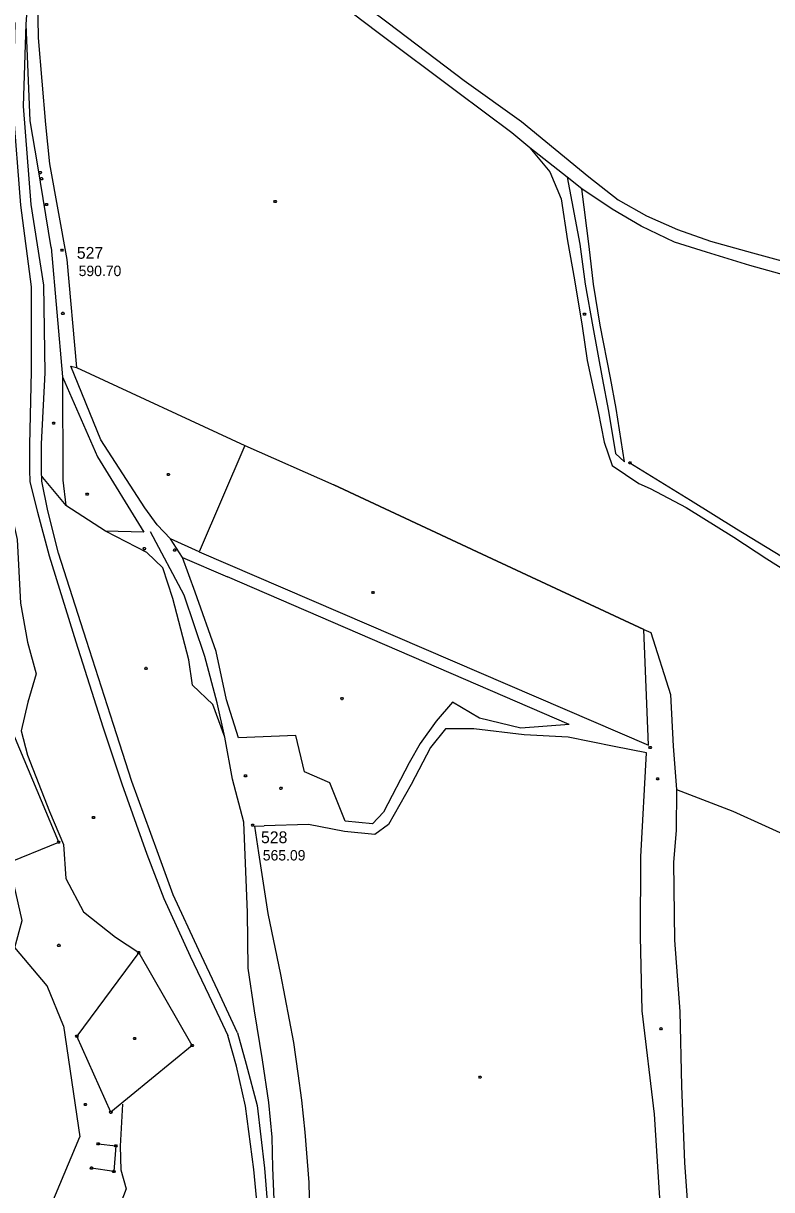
# Model space of a CAD drawing. Extents: x -664960 to -662754, y -993849 to -991145.
# Drawn here: x -663722.6 to -663507.3, y -991825.9 to -991490.5 of the extents above; entities that cross this region are included whole.
import ezdxf

# ---------------------------------------------------------------- set-up
doc = ezdxf.new("R2010")
doc.units = 0
for name, color, linetype in [('Vrstva 1', 7, 'Continuous'), ('Vrstva 12', 7, 'Continuous'), ('Vrstva 13', 7, 'Continuous'), ('Vrstva 18', 7, 'Continuous'), ('Vrstva 27', 7, 'Continuous'), ('Vrstva 28', 7, 'Continuous'), ('Vrstva 63', 7, 'Continuous'), ('Vrstva 8', 7, 'Continuous')]:
    doc.layers.add(name, color=color, linetype=linetype)

msp = doc.modelspace()

# ---------------------------------------------------------------- linework, layer by layer
at = {"layer": 'Vrstva 12'}
for p in [(-663684.075, -991634.708), (-663680.28, -991638.751), (-663672.011, -991642.462)]:
    msp.add_line(p, (-663680.28, -991638.751), dxfattribs=at)
for points in [[(-663684.075, -991634.708), (-663687.678, -991629.824), (-663700.338, -991610.256), (-663708.929, -991589.067), (-663707.354, -991589.5)], [(-663707.354, -991589.5), (-663658.913, -991611.926), (-663672.011, -991642.462)]]:
    msp.add_lwpolyline(points, dxfattribs=at)
at = {"layer": 'Vrstva 13'}
for points in [[(-663649.982, -991541.386), (-663649.802, -991541.686), (-663649.982, -991541.986), (-663650.342, -991541.986), (-663650.522, -991541.686), (-663650.342, -991541.386), (-663649.982, -991541.386)], [(-663711.068, -991573.584), (-663710.888, -991573.884), (-663711.068, -991574.184), (-663711.428, -991574.184), (-663711.608, -991573.884), (-663711.428, -991573.584), (-663711.068, -991573.584)], [(-663560.997, -991573.818), (-663560.817, -991574.118), (-663560.997, -991574.418), (-663561.357, -991574.418), (-663561.537, -991574.118), (-663561.357, -991573.818), (-663560.997, -991573.818)], [(-663713.701, -991605.203), (-663713.521, -991605.503), (-663713.701, -991605.803), (-663714.061, -991605.803), (-663714.241, -991605.503), (-663714.061, -991605.203), (-663713.701, -991605.203)], [(-663680.701, -991619.947), (-663680.521, -991620.247), (-663680.701, -991620.547), (-663681.061, -991620.547), (-663681.241, -991620.247), (-663681.061, -991619.947), (-663680.701, -991619.947)], [(-663704.096, -991625.594), (-663703.916, -991625.894), (-663704.096, -991626.194), (-663704.456, -991626.194), (-663704.636, -991625.894), (-663704.456, -991625.594), (-663704.096, -991625.594)], [(-663687.611, -991641.256), (-663687.431, -991641.556), (-663687.611, -991641.856), (-663687.971, -991641.856), (-663688.151, -991641.556), (-663687.971, -991641.256), (-663687.611, -991641.256)], [(-663621.856, -991653.843), (-663621.676, -991654.143), (-663621.856, -991654.443), (-663622.216, -991654.443), (-663622.396, -991654.143), (-663622.216, -991653.843), (-663621.856, -991653.843)], [(-663687.156, -991675.684), (-663686.976, -991675.984), (-663687.156, -991676.284), (-663687.516, -991676.284), (-663687.696, -991675.984), (-663687.516, -991675.684), (-663687.156, -991675.684)], [(-663630.759, -991684.39), (-663630.579, -991684.69), (-663630.759, -991684.99), (-663631.119, -991684.99), (-663631.299, -991684.69), (-663631.119, -991684.39), (-663630.759, -991684.39)], [(-663539.96, -991707.462), (-663539.78, -991707.762), (-663539.96, -991708.062), (-663540.32, -991708.062), (-663540.5, -991707.762), (-663540.32, -991707.462), (-663539.96, -991707.462)], [(-663648.325, -991710.182), (-663648.145, -991710.482), (-663648.325, -991710.782), (-663648.685, -991710.782), (-663648.865, -991710.482), (-663648.685, -991710.182), (-663648.325, -991710.182)], [(-663702.27, -991718.559), (-663702.09, -991718.859), (-663702.27, -991719.159), (-663702.63, -991719.159), (-663702.81, -991718.859), (-663702.63, -991718.559), (-663702.27, -991718.559)], [(-663712.237, -991755.339), (-663712.057, -991755.639), (-663712.237, -991755.939), (-663712.597, -991755.939), (-663712.777, -991755.639), (-663712.597, -991755.339), (-663712.237, -991755.339)], [(-663538.998, -991779.303), (-663538.818, -991779.603), (-663538.998, -991779.903), (-663539.358, -991779.903), (-663539.538, -991779.603), (-663539.358, -991779.303), (-663538.998, -991779.303)], [(-663690.42, -991782.096), (-663690.24, -991782.396), (-663690.42, -991782.696), (-663690.78, -991782.696), (-663690.96, -991782.396), (-663690.78, -991782.096), (-663690.42, -991782.096)], [(-663591.043, -991793.237), (-663590.863, -991793.537), (-663591.043, -991793.837), (-663591.403, -991793.837), (-663591.583, -991793.537), (-663591.403, -991793.237), (-663591.043, -991793.237)]]:
    msp.add_lwpolyline(points, dxfattribs=at)
at = {"layer": 'Vrstva 18'}
for points in [[(-663711.32, -991555.43), (-663711.14, -991555.73), (-663711.32, -991556.03), (-663711.68, -991556.03), (-663711.86, -991555.73), (-663711.68, -991555.43), (-663711.32, -991555.43)], [(-663678.912, -991641.652), (-663678.732, -991641.952), (-663678.912, -991642.252), (-663679.272, -991642.252), (-663679.452, -991641.952), (-663679.272, -991641.652), (-663678.912, -991641.652)], [(-663542.109, -991698.436), (-663541.929, -991698.736), (-663542.109, -991699.036), (-663542.469, -991699.036), (-663542.649, -991698.736), (-663542.469, -991698.436), (-663542.109, -991698.436)]]:
    msp.add_lwpolyline(points, dxfattribs=at)
at = {"layer": 'Vrstva 27'}
for p, q in [((-663676.38, -991654.949), (-663686.074, -991636.694)), ((-663676.787, -991644.062), (-663680.28, -991638.751))]:
    msp.add_line(p, q, dxfattribs=at)
for points in [[(-663743.58, -991388.419), (-663729.844, -991404.645), (-663713.114, -991418.331), (-663678.355, -991443.741), (-663655.175, -991461.78), (-663640.263, -991473.397), (-663617.672, -991490.323), (-663595.769, -991506.951), (-663579.337, -991518.755), (-663559.944, -991534.662), (-663551.457, -991541.221), (-663543.359, -991545.874), (-663534.399, -991549.773), (-663524.913, -991553.126), (-663512.846, -991556.521), (-663494.937, -991561.373), (-663480.847, -991565.652), (-663469.411, -991569.732), (-663460.126, -991573.712), (-663453.502, -991577.004)], [(-663721.803, -991490.699), (-663720.84, -991477.812), (-663718.854, -991466.022), (-663718.504, -991460.675), (-663718.505, -991441.88), (-663718.268, -991430.911), (-663717.171, -991425.917), (-663712.657, -991423.541), (-663712.511, -991423.464)], [(-663392.708, -991601.995), (-663400.049, -991601.363), (-663406.753, -991599.585), (-663415.923, -991596.415), (-663432.77, -991590.116), (-663442.566, -991585.813), (-663459.978, -991577.759), (-663470.267, -991573.243), (-663482.264, -991568.867), (-663496.396, -991564.917), (-663513.654, -991560.159), (-663526.11, -991556.319), (-663535.27, -991553.444), (-663544.844, -991548.86), (-663553.272, -991543.904), (-663561.986, -991538.065), (-663566.199, -991534.736), (-663576.928, -991526.255), (-663582.099, -991521.945), (-663598.014, -991510.037), (-663620.559, -991493.213), (-663642.167, -991476.69), (-663657.561, -991464.555), (-663680.78, -991446.59)], [(-663725.023, -991490.259), (-663725.672, -991514.595), (-663723.408, -991542.746), (-663720.333, -991566.256), (-663720.41, -991590.539), (-663720.871, -991611.71), (-663720.848, -991618.927), (-663720.775, -991622.299), (-663718.517, -991631.092), (-663715.179, -991643.657), (-663707.528, -991668.323), (-663699.762, -991692.809), (-663694.249, -991709.226), (-663687.136, -991729.457), (-663682.186, -991742.158), (-663674.59, -991758.71), (-663669.244, -991769.946), (-663663.806, -991781.544)], [(-663660.976, -991780.777), (-663666.698, -991768.591), (-663672.116, -991757.062), (-663679.481, -991741.092), (-663684.109, -991728.461), (-663691.37, -991708.516), (-663696.673, -991692.154), (-663704.473, -991667.933), (-663712.493, -991642.902), (-663715.591, -991630.699), (-663717.257, -991622.153), (-663717.407, -991619.031), (-663717.412, -991611.414), (-663716.32, -991591.026), (-663716.728, -991565.825), (-663720.35, -991542.626), (-663722.585, -991514.345), (-663721.803, -991490.699)], [(-663566.199, -991534.736), (-663562.509, -991554.001), (-663561.013, -991565.513), (-663558.832, -991577.786), (-663556.115, -991592.399), (-663554.257, -991602.054), (-663552.237, -991614.213), (-663549.699, -991616.575)], [(-663549.699, -991616.575), (-663552.106, -991601.209), (-663553.666, -991592.418), (-663556.663, -991577.253), (-663558.606, -991565.495), (-663559.81, -991554.685), (-663561.986, -991538.065)], [(-663660.753, -991696.001), (-663664.19, -991685.058), (-663667.141, -991671.167), (-663673.213, -991654.104), (-663676.787, -991644.062)], [(-663664.612, -991695.793), (-663666.865, -991685.925), (-663670.443, -991672.525), (-663676.38, -991654.949)], [(-663652.149, -992072.457), (-663638.894, -992079.322), (-663629.252, -992082.973), (-663622.572, -992083.804), (-663623.507, -992071.963), (-663624.89, -992056.198), (-663630.063, -992031.166), (-663634.545, -992007.215), (-663637.859, -991989.522), (-663641.354, -991966.119), (-663644.017, -991941.494), (-663646.236, -991915.956), (-663649.418, -991889.892), (-663652.546, -991864.285), (-663654.41, -991840.241), (-663656.328, -991820.074), (-663658.665, -991801.934), (-663661.329, -991790.355), (-663663.806, -991781.544)], [(-663660.976, -991780.777), (-663658.558, -991789.771), (-663655.323, -991801.705), (-663653.202, -991819.768), (-663651.587, -991840.172), (-663649.787, -991863.83), (-663646.312, -991889.394), (-663643.411, -991916.091), (-663641.041, -991940.893), (-663638.598, -991965.955), (-663635.066, -991988.904), (-663631.676, -992006.332), (-663627.229, -992030.816), (-663622.18, -992055.438), (-663619.865, -992072.617), (-663618.624, -992084.162), (-663617.662, -992084.005)]]:
    msp.add_lwpolyline(points, dxfattribs=at)
at = {"layer": 'Vrstva 28'}
msp.add_lwpolyline([(-663704.602, -991801.14), (-663704.422, -991801.44), (-663704.602, -991801.74), (-663704.962, -991801.74), (-663705.142, -991801.44), (-663704.962, -991801.14), (-663704.602, -991801.14)], dxfattribs=at)
at = {"layer": 'Vrstva 63'}
for p, q in [((-663714.613, -991554.932), (-663711.385, -991592.178)), ((-663676.787, -991644.062), (-663663.853, -991649.647)), ((-663565.548, -991692.099), (-663663.853, -991649.647)), ((-663656.035, -991721.402), (-663653.311, -991721.311)), ((-663654.862, -991729.013), (-663656.035, -991721.402)), ((-663711.027, -991778.831), (-663706.364, -991810.665)), ((-663696.564, -991820.639), (-663703.007, -991819.676))]:
    msp.add_line(p, q, dxfattribs=at)
for points in [[(-663718.854, -991466.022), (-663718.352, -991494.671), (-663716.242, -991519.605), (-663715.046, -991530.904), (-663710.142, -991558.38), (-663707.354, -991589.5)], [(-663714.613, -991554.932), (-663718.413, -991531.439), (-663720.624, -991518.542), (-663721.803, -991490.699)], [(-663576.928, -991526.255), (-663571.15, -991533.211), (-663567.908, -991540.947), (-663566.098, -991553.032), (-663564.032, -991564.271), (-663561.892, -991577.56), (-663560.448, -991587.485), (-663557.262, -991602.082), (-663555.524, -991610.958), (-663553.194, -991617.648), (-663545.518, -991622.837)], [(-663717.571, -991533.127), (-663717.391, -991533.427), (-663717.571, -991533.727), (-663717.931, -991533.727), (-663718.111, -991533.427), (-663717.931, -991533.127), (-663717.571, -991533.127)], [(-663717.202, -991534.856), (-663717.022, -991535.156), (-663717.202, -991535.456), (-663717.562, -991535.456), (-663717.742, -991535.156), (-663717.562, -991534.856), (-663717.202, -991534.856)], [(-663715.753, -991542.297), (-663715.573, -991542.597), (-663715.753, -991542.897), (-663716.113, -991542.897), (-663716.293, -991542.597), (-663716.113, -991542.297), (-663715.753, -991542.297)], [(-663711.385, -991592.178), (-663711.293, -991621.871), (-663710.35, -991629.178)], [(-663711.385, -991592.178), (-663701.299, -991615.111), (-663687.988, -991636.814), (-663698.995, -991636.547)], [(-663658.913, -991611.926), (-663633.325, -991623.162), (-663589.194, -991643.861), (-663544.069, -991664.786)], [(-663547.936, -991616.556), (-663547.756, -991616.856), (-663547.936, -991617.156), (-663548.296, -991617.156), (-663548.476, -991616.856), (-663548.296, -991616.556), (-663547.936, -991616.556)], [(-663548.116, -991616.856), (-663530.675, -991627.572), (-663517.442, -991635.824), (-663504.686, -991643.622), (-663491.143, -991652.018), (-663479.888, -991659.272)], [(-663728.978, -991620.324), (-663727.884, -991623.391), (-663724.345, -991638.911), (-663723.458, -991657.243), (-663721.409, -991668.442), (-663718.91, -991677.563), (-663721.277, -991685.664), (-663723.199, -991693.925), (-663721.431, -991700.927), (-663715.086, -991717.166), (-663711.105, -991726.622), (-663710.419, -991736.461), (-663705.316, -991746.041), (-663696.082, -991753.303), (-663689.428, -991757.71)], [(-663717.321, -991620.824), (-663717.115, -991621.07), (-663710.35, -991629.178)], [(-663545.518, -991622.837), (-663542.3, -991624.235), (-663531.959, -991629.738), (-663518.182, -991638.283), (-663508.772, -991644.5), (-663502.811, -991648.258), (-663492.706, -991654.085), (-663482.346, -991660.443)], [(-663672.011, -991642.462), (-663542.731, -991698.08), (-663544.069, -991664.786), (-663589.194, -991643.861), (-663633.325, -991623.162)], [(-663659.154, -991720.205), (-663662.424, -991707.812), (-663664.612, -991695.793), (-663668.143, -991686.401), (-663673.909, -991680.836), (-663674.999, -991673.516), (-663679.584, -991655.873), (-663682.494, -991647.062), (-663687.121, -991642.647), (-663698.995, -991636.547), (-663710.35, -991629.178)], [(-663544.069, -991664.786), (-663542.145, -991665.697), (-663536.462, -991683.502), (-663535.712, -991698.318), (-663534.725, -991710.824), (-663534.775, -991722.492), (-663535.558, -991731.788), (-663535.259, -991754.11), (-663533.805, -991774.681), (-663533.296, -991796.178), (-663532.455, -991818.084), (-663530.797, -991841.119), (-663529.041, -991860.69), (-663527.667, -991875.317), (-663525.706, -991893.964), (-663521.207, -991924.894), (-663518.409, -991943.227), (-663513.935, -991973.474), (-663511.498, -991987.024)], [(-663565.548, -991692.099), (-663579.484, -991693.199), (-663591.409, -991690.293), (-663599.14, -991685.693), (-663603.849, -991691.144), (-663608.464, -991697.622), (-663611.611, -991703.159), (-663618.968, -991717.314), (-663622.132, -991720.701), (-663630.009, -991719.914), (-663634.456, -991708.948), (-663641.739, -991705.718), (-663644.215, -991695.302), (-663660.753, -991696.001)], [(-663726.162, -991693.282), (-663744.49, -991718.66), (-663733.482, -991734.819), (-663728.383, -991732.496), (-663712.442, -991725.993), (-663726.162, -991693.282)], [(-663519.147, -992007.037), (-663524.931, -991969.808), (-663528.367, -991946.369), (-663530.939, -991920.02), (-663533.573, -991893.927), (-663536.69, -991861.244), (-663539.224, -991832.857), (-663541.068, -991804.157), (-663544.559, -991774.471), (-663545.028, -991753.079), (-663545.015, -991730.228), (-663543.344, -991700.26), (-663552.681, -991698.483), (-663565.859, -991695.74), (-663578.557, -991695.146), (-663592.996, -991693.333), (-663601.144, -991693.417), (-663605.438, -991698.732), (-663611.051, -991709.356), (-663617.609, -991720.889), (-663621.48, -991723.737), (-663630.201, -991722.923), (-663640.545, -991720.884), (-663653.311, -991721.311)], [(-663658.528, -991706.563), (-663658.348, -991706.863), (-663658.528, -991707.163), (-663658.888, -991707.163), (-663659.068, -991706.863), (-663658.888, -991706.563), (-663658.528, -991706.563)], [(-663534.725, -991710.824), (-663518.545, -991717.031), (-663499.888, -991725.479), (-663483.464, -991732.469), (-663467.097, -991739.167), (-663452.683, -991745.176), (-663439.395, -991749.905), (-663431.74, -991748.578), (-663425.793, -991747.578), (-663419.769, -991746.977), (-663417.071, -991749.271), (-663415.983, -991754.087), (-663415.339, -991761.23), (-663413.882, -991773.433), (-663412.468, -991789.98), (-663411.061, -991800.626), (-663409.93, -991808.068), (-663407.784, -991826.362)], [(-663617.662, -992084.005), (-663617.796, -992070.405), (-663618.685, -992062.035), (-663620.6, -992054.289), (-663624.555, -992034.438), (-663627.573, -992021.077), (-663630.439, -992005.417), (-663633.594, -991988.6), (-663636.017, -991965.823), (-663639.158, -991940.551), (-663641.433, -991916.279), (-663644.548, -991888.909), (-663648.221, -991863.623), (-663649.938, -991840.103), (-663650.821, -991819.63), (-663650.995, -991810.793), (-663652.021, -991800.876), (-663653.776, -991788.518), (-663656.114, -991774.485), (-663657.935, -991762.249), (-663658.157, -991746.16), (-663659.154, -991720.205)], [(-663712.262, -991725.693), (-663712.082, -991725.993), (-663712.262, -991726.293), (-663712.622, -991726.293), (-663712.802, -991725.993), (-663712.622, -991725.693), (-663712.262, -991725.693)], [(-663625.612, -991996.822), (-663628.083, -991983.066), (-663630.213, -991966.493), (-663632.388, -991949.185), (-663633.288, -991930.636), (-663633.176, -991910.364), (-663633.262, -991895.715), (-663634.553, -991883.925), (-663637.482, -991872.717), (-663638.916, -991862.418), (-663640.047, -991841.399), (-663640.409, -991823.803), (-663641.52, -991809.389), (-663642.527, -991800.158), (-663643.533, -991792.531), (-663644.831, -991783.57), (-663648.588, -991764.05), (-663652.178, -991746.436), (-663654.862, -991729.013)], [(-663711.027, -991778.831), (-663715.739, -991767.325), (-663725.062, -991756.231), (-663722.908, -991748.505), (-663725.274, -991738.301), (-663728.383, -991732.496)], [(-663674.071, -991784.413), (-663689.428, -991757.71), (-663707.225, -991781.758)], [(-663689.248, -991757.41), (-663689.068, -991757.71), (-663689.248, -991758.01), (-663689.608, -991758.01), (-663689.788, -991757.71), (-663689.608, -991757.41), (-663689.248, -991757.41)], [(-663707.045, -991781.458), (-663706.865, -991781.758), (-663707.045, -991782.058), (-663707.405, -991782.058), (-663707.585, -991781.758), (-663707.405, -991781.458), (-663707.045, -991781.458)], [(-663674.071, -991784.413), (-663697.468, -991803.659), (-663707.225, -991781.758)], [(-663673.891, -991784.113), (-663673.711, -991784.413), (-663673.891, -991784.713), (-663674.251, -991784.713), (-663674.431, -991784.413), (-663674.251, -991784.113), (-663673.891, -991784.113)], [(-663697.288, -991803.359), (-663697.108, -991803.659), (-663697.288, -991803.959), (-663697.648, -991803.959), (-663697.828, -991803.659), (-663697.648, -991803.359), (-663697.288, -991803.359)], [(-663694.1, -991801.285), (-663694.758, -991813.43), (-663694.534, -991820.204), (-663692.989, -991825.647), (-663694.588, -991829.662)], [(-663737.283, -991824.672), (-663732.19, -991837.962), (-663717.901, -991838.173), (-663706.364, -991810.665)], [(-663700.914, -991812.4), (-663700.734, -991812.7), (-663700.914, -991813), (-663701.274, -991813), (-663701.454, -991812.7), (-663701.274, -991812.4), (-663700.914, -991812.4)], [(-663701.094, -991812.7), (-663696.024, -991813.316), (-663696.564, -991820.639)], [(-663695.844, -991813.016), (-663695.664, -991813.316), (-663695.844, -991813.616), (-663696.204, -991813.616), (-663696.384, -991813.316), (-663696.204, -991813.016), (-663695.844, -991813.016)], [(-663702.827, -991819.376), (-663702.647, -991819.676), (-663702.827, -991819.976), (-663703.187, -991819.976), (-663703.367, -991819.676), (-663703.187, -991819.376), (-663702.827, -991819.376)], [(-663696.384, -991820.339), (-663696.204, -991820.639), (-663696.384, -991820.939), (-663696.744, -991820.939), (-663696.924, -991820.639), (-663696.744, -991820.339), (-663696.384, -991820.339)]]:
    msp.add_lwpolyline(points, dxfattribs=at)
at = {"layer": 'Vrstva 8'}
for points in [[(-663711.32, -991555.43), (-663711.14, -991555.73), (-663711.32, -991556.03), (-663711.68, -991556.03), (-663711.86, -991555.73), (-663711.68, -991555.43), (-663711.32, -991555.43)], [(-663656.47, -991720.76), (-663656.29, -991721.06), (-663656.47, -991721.36), (-663656.83, -991721.36), (-663657.01, -991721.06), (-663656.83, -991720.76), (-663656.47, -991720.76)]]:
    msp.add_lwpolyline(points, dxfattribs=at)

# ---------------------------------------------------------------- texts
at = {"layer": 'Vrstva 1'}
for s, p in [('527', (-663707.222, -991558.192)), ('528', (-663654.25, -991726.26))]:
    msp.add_text(s, height=3.4, dxfattribs=at).set_placement(p)
at = {"layer": 'Vrstva 63'}
for s, p in [('590.70', (-663706.698, -991563.172)), ('565.09', (-663653.726, -991731.24))]:
    msp.add_text(s, height=3, dxfattribs=at).set_placement(p)

doc.saveas('drawing.dxf')
